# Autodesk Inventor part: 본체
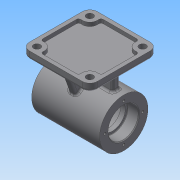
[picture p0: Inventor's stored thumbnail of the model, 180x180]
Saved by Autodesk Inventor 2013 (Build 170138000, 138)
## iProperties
Created: 2019-06
Part Number: 본체
Material: 일반
Document SubType Name: Modeling
Designer: Administrator
Density: 1 g/cm^3
Author: Administrator
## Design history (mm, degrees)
sketch "스케치1"
  geometry: L1 (-45, 32)-(0, 32); L2 (0, 32)-(0, 0); L3 (0, 0)-(-45, 0); L4 (-45, 0)-(-45, 32); L5 (-45, 20)-(-30, 20); L6 (-30, 20)-(-30, 17); L7 (-30, 17)-(-24, 17); L8 (-24, 17)-(-24, 25); L9 (-24, 25)-(0, 25); 1 further point
  constraints: 18 end point, 4 parallel, 4 perpendicular, 2 point on line, 1 coincident, 1 horizontal
  dimensions: "d0" = 64 diameter of L1 L3; "d2" = 45 distance of L1.start L1.end; "d3" = 40 diameter of L5 L3; "d4" = 34 diameter of L7 L3; "d5" = 50 diameter of L9 L3; "d6" = 15 distance between parallel lines of L6 L4; "d7" = 6 distance of L6.end L7.end
revolve "회전1" sketch "스케치1" stored, may be unused: angle "d8" = 90 deg
sketch "스케치2"
  geometry: L1 (0, 0)-(0, 25); C1 r 20 at (0, 0) reference
  constraints: 2 end point, 1 vertical
  dimensions: "d9" = 25 distance of L1.start L1.end
hole "구멍1" sketch "스케치2" at (0, 25) diameter "d10" = 3.242; stored, may be unused: countersink angle "d14" = 90 deg, drill point angle "d16" = 118 deg; dims "d11" = 7, "d12" = 4, "d13" = 2, "d15" = 9
chamfer "모따기1" distance "d20" = 1; stored, may be unused: second distance "d21" = 2, angle "d22" = 45 deg
fillet "모깎기1" dims "d23" = 0.6
fillet "모깎기2" dims "d24" = 3
sketch "스케치3"
  geometry: 1 further point
node "작업 평면1"
sketch "스케치4"
  geometry: C1 r 5 at (0, 0); 1 further point
  constraints: 1 centre point, 1 coincident
  dimensions: "d26" = 10 diameter of C1
extrude "돌출1" join sketch "스케치4" stored distance "d27" = 10; taper "d28" = 0 deg
sketch "스케치5"
  geometry: C1 r 5 at (0, 0) reference
hole "구멍2" sketch "스케치5" at (0, 0) diameter "d29" = 4.917; stored, may be unused: countersink angle "d33" = 90 deg, drill point angle "d35" = 118 deg; dims "d30" = 30, "d31" = 4, "d32" = 2, "d34" = 30
fillet "모깎기3" dims "d36" = 2
node "작업 평면2"
sketch "스케치6"
  geometry: L1 (-45, -45)-(45, -45); L2 (45, -45)-(45, 45); L3 (45, 45)-(-45, 45); L4 (-45, 45)-(-45, -45); L5 (-45, -45)-(45, 45); L6 (45, -45)-(-45, 45); 1 further point
  constraints: 12 end point, 2 midpoint, 2 parallel, 1 horizontal, 1 perpendicular
  dimensions: "d38" = 90 distance of L3.end L2.end; "d39" = 90 distance of L2.end L1.end
extrude "돌출2" join sketch "스케치6" distance "d40" = 10; taper "d41" = 0 deg
sketch "스케치7"
  geometry: L1 (-35, 5)-(35, 5); L2 (35, 5)-(35, -5); L3 (35, -5)-(-35, -5); L4 (-35, -5)-(-35, 5); 3 further points
  constraints: 8 end point, 2 midpoint, 2 parallel, 1 horizontal, 1 horizontal alignment, 1 perpendicular, 1 vertical alignment
  dimensions: "d42" = 10 distance of L1.end L2.end; "d44" = 70 distance of L1.start L1.end
extrude "돌출3" join sketch "스케치7" stored distance "d45" = 10; taper "d46" = 0 deg
sketch "스케치8"
  geometry: L1 (28.098, 36.038)-(35, 55); L2 (-2.458, -24.879)-(-2.458, -35) reference; L3 (-2.458, -35)-(-5, -35) reference; L4 (-5, -35)-(-5, -33.272) reference; L5 (-5, 31.607)-(-5, 55) reference; L6 (-5, 55)-(-45, 55) reference; L7 (-45, 55)-(-45, 65) reference; L8 (-45, 65)-(45, 65) reference; L9 (45, 65)-(45, 55) reference; L10 (45, 55)-(5, 55) reference; L11 (5, 55)-(5, 31.607) reference; L12 (5, -33.272)-(5, -35) reference; L13 (5, -35)-(2.458, -35) reference; L14 (2.458, -35)-(2.458, -24.879) reference; A1 r 25 centre (0, 0) between (2.458, -24.879) and (-2.458, -24.879) reference; A2 r 32 centre (0, 0) between (-5, 31.607) and (-6.588, -31.314) reference; A3 r 32 centre (0, 0) between (6.588, -31.314) and (5, 31.607) reference; 1 further point
  constraints: 2 end point, 1 point on line, 2 other
  dimensions: "d47" = 10 distance from line of L1.end L9; "d48" = 110 deg angle of L1 L10
feature "리브1" sketch "스케치8" dims "d49" = 1, "d50" = 10, "d51" = 0, "d52" = 0, "d53" = 1, "d54" = 1
fillet "모깎기4" dims "d55" = 3
fillet "모깎기5" dims "d56" = 3
fillet "모깎기6" dims "d57" = 10
sketch "스케치9"
  geometry: C1 r 4.5 at (-35, 35); C2 r 4.5 at (35, 35); A1 r 10 centre (35, 35) between (45, 35) and (35, 45) reference; A2 r 10 centre (-35, 35) between (-35, 45) and (-45, 35) reference; 1 further point
  constraints: 2 centre point, 2 coincident
  dimensions: "d58" = 9 diameter of C1; "d59" = 9 diameter of C2
extrude "돌출4" cut sketch "스케치9" stored distance "d60" = 10; taper "d61" = 0 deg
fillet "모깎기7" dims "d62" = 3
sketch "스케치10"
  geometry: L1 (-26.34, -40)-(26.34, -40); L2 (40, -26.34)-(40, 26.34); L3 (26.34, 40)-(-26.34, 40); L4 (-40, 26.34)-(-40, -26.34); L5 (-40, -40)-(40, 40); L6 (40, -40)-(-40, 40); A1 r 10 centre (-35, -35) between (-45, -35) and (-35, -45) reference; A2 r 10 centre (35, -35) between (35, -45) and (45, -35) reference; A3 r 10 centre (35, 35) between (45, 35) and (35, 45) reference; A4 r 10 centre (-35, 35) between (-35, 45) and (-45, 35) reference; A5 r 10 centre (-35, 35) between (-26.34, 40) and (-40, 26.34); A6 r 10 centre (35, 35) between (26.34, 40) and (40, 26.34); A7 r 10 centre (35, -35) between (40, -26.34) and (26.34, -40); A8 r 10 centre (-35, -35) between (-26.34, -40) and (-40, -26.34); 1 further point
  constraints: 12 end point, 8 point on circle, 4 centre point, 4 coincident, 2 midpoint, 2 parallel, 1 horizontal, 1 perpendicular
  dimensions: "d63" = 80 distance of L5.end L6.end; "d65" = 80 distance of L6.start L5.end; "d66" = 20 diameter of A5; "d67" = 20 diameter of A6; "d68" = 20 diameter of A7; "d69" = 20 diameter of A8
extrude "돌출5" cut sketch "스케치10" distance "d70" = 5; taper "d71" = 0 deg
fillet "모깎기8" dims "d72" = 3
sketch "스케치11"
  geometry: L1 (70, 0)-(0, 0) reference; L2 (-10, 7)-(-10, 0) reference; 2 further points
  constraints: 1 other
  dimensions: "d73" = 45 distance from line of point (35, 4) L2; "d74" = 4 distance from line of L1 point (35, 4)
feature "엠보싱1" sketch "스케치11" dims "d0" = 64, "d2" = 45, "d3" = 40, "d4" = 34, "d5" = 50, "d6" = 15, "d7" = 6, "d75" = 0.5, "d76" = 0
node "솔리드1"
pattern_circular "원형 패턴1" dims angle "d18" = 360 deg
mirror "대칭1"
mirror "대칭2"
mirror "대칭3"
node "절단 모서리 투영1"
other parameters: "d25" = -35, "d37" = 65
